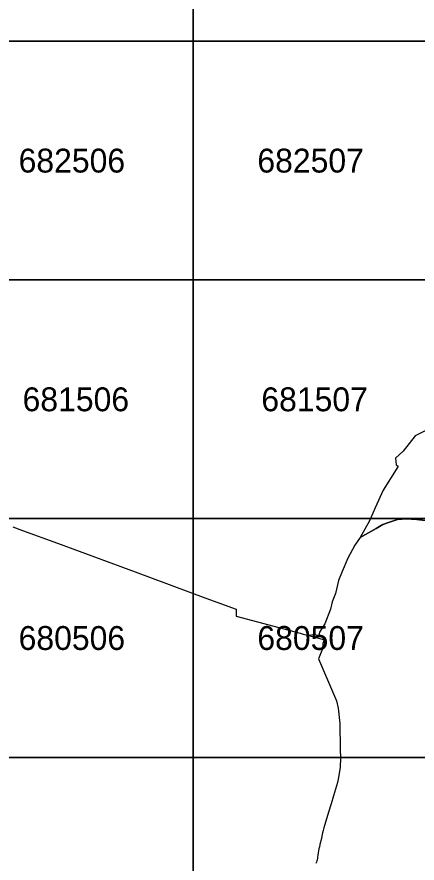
# Model space of a CAD drawing. Extents: x 25485000 to 25520000, y 6656775 to 6690000.
# Drawn here: x 25506262 to 25507937, y 6679557 to 6683102 of the extents above; entities that cross this region are included whole.
import ezdxf

# ---------------------------------------------------------------- set-up
doc = ezdxf.new("R2010")
doc.units = 0
doc.layers.add('Level 63', color=7, linetype='Continuous')

msp = doc.modelspace()

# ---------------------------------------------------------------- linework, layer by layer
at = {"layer": 'Level 63'}
for points in [[(25506000, 6683000), (25507000, 6683000), (25507000, 6684000), (25506000, 6684000)], [(25507000, 6683000), (25508000, 6683000), (25508000, 6684000), (25507000, 6684000)], [(25506000, 6682000), (25507000, 6682000), (25507000, 6683000), (25506000, 6683000)], [(25507000, 6682000), (25508000, 6682000), (25508000, 6683000), (25507000, 6683000)], [(25506000, 6681000), (25507000, 6681000), (25507000, 6682000), (25506000, 6682000)], [(25507000, 6681000), (25508000, 6681000), (25508000, 6682000), (25507000, 6682000)], [(25506000, 6680000), (25507000, 6680000), (25507000, 6681000), (25506000, 6681000)], [(25507000, 6680000), (25508000, 6680000), (25508000, 6681000), (25507000, 6681000)], [(25506000, 6679000), (25507000, 6679000), (25507000, 6680000), (25506000, 6680000)], [(25507000, 6679000), (25508000, 6679000), (25508000, 6680000), (25507000, 6680000)]]:
    msp.add_lwpolyline(points, close=True, dxfattribs=at)
for points in [[(25508013.4, 6681388.6), (25507929.6, 6681346.4), (25507879.1, 6681283.4), (25507847.1, 6681252.8), (25507849.2, 6681225.1), (25507857.9, 6681220.1), (25507849.4, 6681206.5), (25507795.4, 6681119.5), (25507761.8, 6681045.6), (25507738.6, 6680990.8), (25507699, 6680921.6), (25507766.3, 6680958.3), (25507794.6, 6680974.9), (25507821.9, 6680985.5), (25507855.8, 6680996), (25507891.4, 6680998.7), (25507935.9, 6680997), (25507971.5, 6680992.5)], [(25507971.5, 6680992.5), (25507935.9, 6680997), (25507891.4, 6680998.7), (25507855.8, 6680996), (25507821.9, 6680985.5), (25507794.6, 6680974.9), (25507766.3, 6680958.3), (25507699, 6680921.6), (25507676.4, 6680888.5), (25507647.1, 6680835.1), (25507623.7, 6680778.8), (25507608.1, 6680741.3), (25507595.4, 6680686.9), (25507582.2, 6680651.3), (25507574.6, 6680621.2), (25507551.1, 6680559.4), (25507529.2, 6680525.1), (25507525.8, 6680511.1), (25507504.9, 6680513.1), (25507484.5, 6680509.9), (25507530.7, 6680497.5), (25507543.7, 6680494), (25507548, 6680491.5), (25507542.8, 6680477.6), (25507541.2, 6680454.2), (25507524.8, 6680413.3), (25507600, 6680236.5), (25507606.5, 6680206.4), (25507613.6, 6680141.7), (25507615.9, 6680033.7), (25507616.3, 6679996.1), (25507615.3, 6679958.6), (25507608, 6679915.2), (25507603.5, 6679895.2), (25507587.1, 6679839.2), (25507577.2, 6679805), (25507567, 6679769.8), (25507547.3, 6679704.8), (25507543.7, 6679693.2), (25507541.7, 6679684.4), (25507538.5, 6679669.7), (25507536.6, 6679660.8), (25507530.3, 6679634.6), (25507528.1, 6679625.8), (25507526, 6679617.2), (25507524.1, 6679608.3), (25507523, 6679599.4), (25507521.6, 6679590.4), (25507520.5, 6679581.5), (25507520, 6679576), (25507518.8, 6679570.4), (25507517.6, 6679566.4), (25507515.5, 6679561.1), (25507513.1, 6679555.6)], [(25506243.7, 6680965.7), (25506285, 6680950.6), (25506430.8, 6680897.1), (25506640, 6680819.9), (25506756.7, 6680776.7), (25507053.2, 6680666.9), (25507180, 6680620.2), (25507179.5, 6680591.6), (25507447.8, 6680519.7), (25507460.4, 6680516.4), (25507484.5, 6680509.9), (25507530.7, 6680497.5), (25507543.7, 6680494), (25507548, 6680491.5), (25507542.8, 6680477.6), (25507541.2, 6680454.2), (25507524.8, 6680413.3), (25507600, 6680236.5), (25507606.5, 6680206.4), (25507613.6, 6680141.7), (25507615.9, 6680033.7), (25507616.3, 6679996.1), (25507615.3, 6679958.6), (25507608, 6679915.2), (25507603.5, 6679895.2), (25507587.1, 6679839.2), (25507577.2, 6679805), (25507567, 6679769.8), (25507547.3, 6679704.8), (25507543.7, 6679693.2), (25507541.7, 6679684.4), (25507538.5, 6679669.7), (25507536.6, 6679660.8), (25507530.3, 6679634.6), (25507528.1, 6679625.8), (25507526, 6679617.2), (25507524.1, 6679608.3), (25507523, 6679599.4), (25507521.6, 6679590.4), (25507520.5, 6679581.5), (25507520, 6679576), (25507518.8, 6679570.4), (25507517.6, 6679566.4), (25507515.5, 6679561.1), (25507513.1, 6679555.6)]]:
    msp.add_lwpolyline(points, dxfattribs=at)

# ---------------------------------------------------------------- texts
for s, p in [('682506', (25506268.5, 6682450)), ('682507', (25507268.5, 6682450)), ('681506', (25506285.1, 6681450)), ('681507', (25507285.1, 6681450)), ('680506', (25506268.5, 6680450)), ('680507', (25507268.5, 6680450))]:
    msp.add_text(s, height=100, dxfattribs=at).set_placement(p)

doc.saveas('drawing.dxf')
